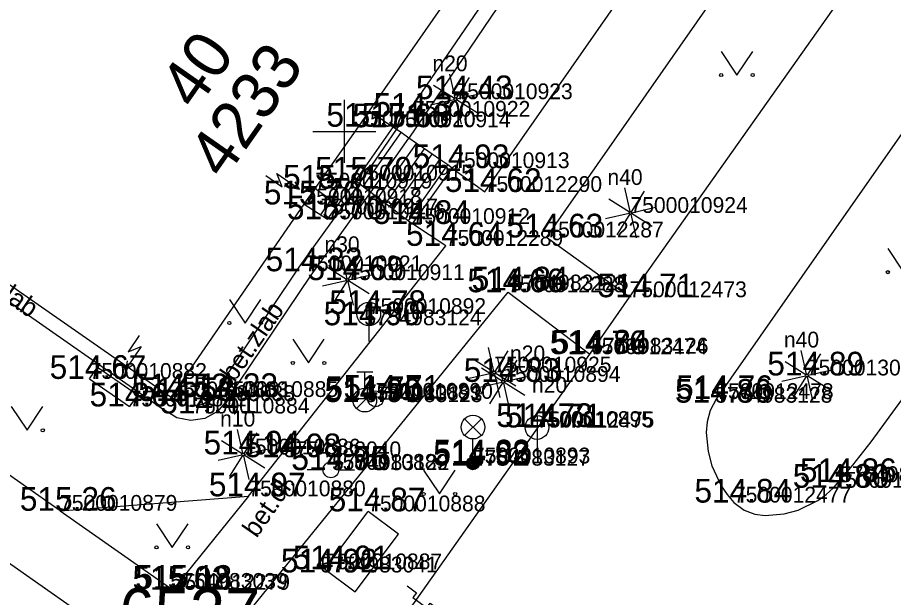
# Model space of a CAD drawing. Extents: x -669251 to -668549, y -1128351 to -1127698.
# Drawn here: x -668960.36 to -668932.59, y -1127964.76 to -1127946.39 of the extents above; entities that cross this region are included whole.
import ezdxf

# ---------------------------------------------------------------- set-up
doc = ezdxf.new("R2010")
doc.units = 0
for name, color, linetype in [('Vrstva 1', 7, 'Continuous'), ('Vrstva 10', 7, 'Continuous'), ('Vrstva 11', 7, 'Continuous'), ('Vrstva 14', 7, 'Continuous'), ('Vrstva 2', 7, 'Continuous'), ('Vrstva 22', 7, 'Continuous'), ('Vrstva 24', 7, 'Continuous'), ('Vrstva 27', 7, 'Continuous'), ('Vrstva 28', 7, 'Continuous'), ('Vrstva 3', 7, 'Continuous'), ('Vrstva 33', 7, 'Continuous'), ('Vrstva 36', 7, 'Continuous'), ('Vrstva 40', 7, 'Continuous'), ('Vrstva 43', 7, 'Continuous'), ('Vrstva 44', 7, 'Continuous'), ('Vrstva 47', 7, 'Continuous'), ('Vrstva 5', 7, 'Continuous'), ('Vrstva 6', 7, 'Continuous'), ('Vrstva 61', 7, 'Continuous'), ('Vrstva 63', 7, 'Continuous')]:
    doc.layers.add(name, color=color, linetype=linetype)

msp = doc.modelspace()

# ---------------------------------------------------------------- linework, layer by layer
at = {"layer": 'Vrstva 1'}
for p, q in [((-668946.478, -1127948.979), (-668946.478, -1127948.979)), ((-668947.823, -1127949.536), (-668947.823, -1127949.536)), ((-668949.554, -1127949.85), (-668949.554, -1127949.85)), ((-668948.449, -1127949.868), (-668948.449, -1127949.868)), ((-668946.578, -1127951.163), (-668946.578, -1127951.163)), ((-668949.639, -1127951.558), (-668949.639, -1127951.558)), ((-668950.927, -1127951.811), (-668950.927, -1127951.811)), ((-668945.547, -1127951.918), (-668945.547, -1127951.918)), ((-668951.264, -1127952.313), (-668951.264, -1127952.313)), ((-668950.752, -1127952.627), (-668950.752, -1127952.627)), ((-668940.929, -1127952.582), (-668940.929, -1127952.582)), ((-668950.533, -1127952.785), (-668950.533, -1127952.785)), ((-668947.834, -1127952.932), (-668947.834, -1127952.932)), ((-668943.593, -1127953.358), (-668943.593, -1127953.358)), ((-668946.78, -1127953.625), (-668946.78, -1127953.625)), ((-668951.243, -1127954.43), (-668951.243, -1127954.43)), ((-668949.9, -1127954.71), (-668949.9, -1127954.71)), ((-668944.811, -1127955.095), (-668944.811, -1127955.095)), ((-668944.71, -1127955.038), (-668944.71, -1127955.038)), ((-668940.958, -1127955.253), (-668940.958, -1127955.253)), ((-668949.225, -1127955.784), (-668949.225, -1127955.784)), ((-668949.367, -1127956.141), (-668949.367, -1127956.141)), ((-668942.213, -1127957.057), (-668942.213, -1127957.057)), ((-668942.174, -1127957.038), (-668942.174, -1127957.038)), ((-668945.249, -1127957.636), (-668945.249, -1127957.636)), ((-668958.076, -1127957.84), (-668958.076, -1127957.84)), ((-668944.963, -1127957.935), (-668944.963, -1127957.935)), ((-668935.335, -1127957.731), (-668935.335, -1127957.731)), ((-668955.487, -1127958.423), (-668955.487, -1127958.423)), ((-668953.915, -1127958.413), (-668953.915, -1127958.413)), ((-668949.01, -1127958.47), (-668949.01, -1127958.47)), ((-668938.208, -1127958.478), (-668938.208, -1127958.478)), ((-668956.81, -1127958.713), (-668956.81, -1127958.713)), ((-668955.283, -1127958.542), (-668955.283, -1127958.542)), ((-668949.35, -1127958.513), (-668949.35, -1127958.513)), ((-668949.34, -1127958.574), (-668949.34, -1127958.574)), ((-668938.245, -1127958.594), (-668938.245, -1127958.594)), ((-668954.822, -1127958.936), (-668954.822, -1127958.936)), ((-668943.933, -1127959.364), (-668943.933, -1127959.364)), ((-668943.891, -1127959.38), (-668943.891, -1127959.38)), ((-668953.208, -1127960.235), (-668953.208, -1127960.235)), ((-668951.916, -1127960.321), (-668951.916, -1127960.321)), ((-668950.425, -1127960.72), (-668950.425, -1127960.72)), ((-668945.932, -1127960.588), (-668945.932, -1127960.588)), ((-668945.921, -1127960.518), (-668945.921, -1127960.518)), ((-668950.391, -1127960.731), (-668950.391, -1127960.731)), ((-668934.283, -1127961.109), (-668934.283, -1127961.109)), ((-668953.041, -1127961.56), (-668953.041, -1127961.56)), ((-668934.496, -1127961.289), (-668934.496, -1127961.289)), ((-668937.649, -1127961.759), (-668937.649, -1127961.759)), ((-668959.013, -1127962.018), (-668959.013, -1127962.018)), ((-668949.244, -1127962.037), (-668949.244, -1127962.037)), ((-668950.757, -1127963.972), (-668950.757, -1127963.972)), ((-668950.618, -1127963.872), (-668950.618, -1127963.872)), ((-668955.515, -1127964.491), (-668955.515, -1127964.491)), ((-668955.442, -1127964.522), (-668955.442, -1127964.522))]:
    msp.add_line(p, q, dxfattribs=at)
at = {"layer": 'Vrstva 10'}
for p, q in [((-668939.036, -1127937.065), (-668947.956, -1127950.209)), ((-668948.347, -1127949.939), (-668940.177, -1127938.02)), ((-668945.547, -1127951.918), (-668936.445, -1127938.885)), ((-668943.593, -1127953.358), (-668934.469, -1127940.308)), ((-668940.958, -1127955.253), (-668934.167, -1127945.646)), ((-668949.52, -1127951.649), (-668948.347, -1127949.939)), ((-668946.578, -1127951.163), (-668945.547, -1127951.918)), ((-668951.43, -1127954.305), (-668949.52, -1127951.649)), ((-668951.056, -1127954.555), (-668949.161, -1127951.922)), ((-668965.097, -1127952.276), (-668955.699, -1127958.834)), ((-668946.78, -1127953.625), (-668947.834, -1127952.932)), ((-668940.958, -1127955.253), (-668943.593, -1127953.358)), ((-668953.041, -1127961.56), (-668946.78, -1127953.625)), ((-668954.108, -1127958.297), (-668951.43, -1127954.305)), ((-668953.722, -1127958.529), (-668951.056, -1127954.555)), ((-668954.992, -1127967.628), (-668944.811, -1127955.095)), ((-668944.811, -1127955.095), (-668942.213, -1127957.057)), ((-668942.213, -1127957.057), (-668940.958, -1127955.253)), ((-668953.041, -1127961.56), (-668955.442, -1127964.522)), ((-668959.013, -1127962.018), (-668955.442, -1127964.522))]:
    msp.add_line(p, q, dxfattribs=at)
for points in [[(-668930.916, -1127948.056), (-668934.562, -1127953.267), (-668938.208, -1127958.478), (-668938.4, -1127958.846), (-668938.494, -1127959.204), (-668938.524, -1127959.537), (-668938.47, -1127960.14), (-668938.349, -1127960.59), (-668938.055, -1127961.223), (-668937.864, -1127961.507), (-668937.649, -1127961.759), (-668937.322, -1127961.999), (-668936.983, -1127962.121), (-668936.658, -1127962.165), (-668936.058, -1127962.12), (-668935.608, -1127961.996), (-668934.986, -1127961.695), (-668934.72, -1127961.503), (-668934.496, -1127961.289), (-668933.884, -1127960.578), (-668933.298, -1127959.833), (-668931.64, -1127957.566)], [(-668959.013, -1127962.018), (-668967.919, -1127955.77)], [(-668969.098, -1127957.738), (-668962.045, -1127962.683), (-668954.992, -1127967.628), (-668954.609, -1127967.856), (-668954.246, -1127968.014), (-668953.566, -1127968.2), (-668953.035, -1127968.266), (-668952.24, -1127968.256), (-668951.488, -1127968.119), (-668950.77, -1127967.878), (-668950.239, -1127967.633), (-668949.859, -1127967.411), (-668949.342, -1127967.014), (-668948.918, -1127966.536), (-668945.566, -1127961.796), (-668942.213, -1127957.057)], [(-668955.487, -1127958.423), (-668955.188, -1127958.64), (-668954.826, -1127958.711), (-668954.467, -1127958.625), (-668954.178, -1127958.396), (-668954.108, -1127958.297)], [(-668953.722, -1127958.529), (-668954.02, -1127958.872), (-668954.418, -1127959.091), (-668954.867, -1127959.161), (-668955.312, -1127959.071), (-668955.699, -1127958.834)]]:
    msp.add_lwpolyline(points, dxfattribs=at)
at = {"layer": 'Vrstva 11'}
for p, q in [((-668949.201, -1127949.344), (-668948.449, -1127949.868)), ((-668949.639, -1127951.558), (-668948.449, -1127949.868)), ((-668948.347, -1127949.939), (-668948.449, -1127949.868)), ((-668949.4, -1127951.74), (-668948.202, -1127950.039)), ((-668948.202, -1127950.039), (-668948.347, -1127949.939)), ((-668947.956, -1127950.209), (-668948.202, -1127950.039)), ((-668949.161, -1127951.922), (-668947.956, -1127950.209)), ((-668948.922, -1127952.104), (-668947.709, -1127950.38)), ((-668947.709, -1127950.38), (-668947.956, -1127950.209)), ((-668947.462, -1127950.551), (-668947.709, -1127950.38)), ((-668948.684, -1127952.285), (-668947.462, -1127950.551)), ((-668948.445, -1127952.467), (-668947.216, -1127950.722)), ((-668947.216, -1127950.722), (-668947.462, -1127950.551)), ((-668946.969, -1127950.892), (-668947.216, -1127950.722)), ((-668948.206, -1127952.649), (-668946.969, -1127950.892)), ((-668946.722, -1127951.063), (-668946.969, -1127950.892)), ((-668947.967, -1127952.831), (-668946.722, -1127951.063)), ((-668947.834, -1127952.932), (-668946.578, -1127951.163)), ((-668946.578, -1127951.163), (-668946.722, -1127951.063)), ((-668950.533, -1127952.785), (-668949.639, -1127951.558)), ((-668949.639, -1127951.558), (-668949.52, -1127951.649)), ((-668949.52, -1127951.649), (-668949.4, -1127951.74)), ((-668949.4, -1127951.74), (-668949.161, -1127951.922)), ((-668949.161, -1127951.922), (-668948.922, -1127952.104)), ((-668948.922, -1127952.104), (-668948.684, -1127952.285)), ((-668951.27, -1127952.309), (-668950.533, -1127952.785)), ((-668948.684, -1127952.285), (-668948.445, -1127952.467)), ((-668948.445, -1127952.467), (-668948.206, -1127952.649)), ((-668948.206, -1127952.649), (-668947.967, -1127952.831)), ((-668947.967, -1127952.831), (-668947.834, -1127952.932))]:
    msp.add_line(p, q, dxfattribs=at)
at = {"layer": 'Vrstva 14'}
msp.add_line((-668959.013, -1127962.018), (-668953.041, -1127961.56), dxfattribs=at)
at = {"layer": 'Vrstva 22'}
for p, q in [((-668946.486, -1127948.939), (-668946.658, -1127948.185)), ((-668946.044, -1127948.289), (-668946.458, -1127948.945)), ((-668946.512, -1127948.959), (-668947.168, -1127948.545)), ((-668947.272, -1127949.159), (-668946.518, -1127948.987)), ((-668946.498, -1127949.013), (-668946.912, -1127949.669)), ((-668946.47, -1127949.019), (-668946.298, -1127949.773)), ((-668945.788, -1127949.413), (-668946.444, -1127948.999)), ((-668946.438, -1127948.971), (-668945.684, -1127948.799)), ((-668940.937, -1127952.542), (-668941.109, -1127951.788)), ((-668940.495, -1127951.892), (-668940.909, -1127952.548)), ((-668940.963, -1127952.562), (-668941.619, -1127952.148)), ((-668941.723, -1127952.762), (-668940.969, -1127952.59)), ((-668940.949, -1127952.616), (-668941.363, -1127953.272)), ((-668940.921, -1127952.622), (-668940.749, -1127953.376)), ((-668940.239, -1127953.016), (-668940.895, -1127952.602)), ((-668940.889, -1127952.574), (-668940.135, -1127952.402)), ((-668949.908, -1127954.67), (-668950.08, -1127953.916)), ((-668949.466, -1127954.02), (-668949.88, -1127954.676)), ((-668949.934, -1127954.69), (-668950.59, -1127954.276)), ((-668949.86, -1127954.702), (-668949.106, -1127954.53)), ((-668950.694, -1127954.89), (-668949.94, -1127954.718)), ((-668949.92, -1127954.744), (-668950.334, -1127955.4)), ((-668949.892, -1127954.75), (-668949.72, -1127955.504)), ((-668949.21, -1127955.144), (-668949.866, -1127954.73)), ((-668945.257, -1127957.596), (-668945.429, -1127956.842)), ((-668944.815, -1127956.946), (-668945.229, -1127957.602)), ((-668935.343, -1127957.691), (-668935.515, -1127956.937)), ((-668934.901, -1127957.041), (-668935.315, -1127957.697)), ((-668945.283, -1127957.616), (-668945.939, -1127957.202)), ((-668944.971, -1127957.895), (-668945.143, -1127957.141)), ((-668944.529, -1127957.245), (-668944.943, -1127957.901)), ((-668935.369, -1127957.711), (-668936.025, -1127957.297)), ((-668946.043, -1127957.816), (-668945.289, -1127957.644)), ((-668945.269, -1127957.67), (-668945.683, -1127958.326)), ((-668944.997, -1127957.915), (-668945.653, -1127957.501)), ((-668944.559, -1127958.07), (-668945.215, -1127957.656)), ((-668945.209, -1127957.628), (-668944.455, -1127957.456)), ((-668935.295, -1127957.723), (-668934.541, -1127957.551)), ((-668945.757, -1127958.115), (-668945.003, -1127957.943)), ((-668945.241, -1127957.676), (-668945.069, -1127958.43)), ((-668944.923, -1127957.927), (-668944.169, -1127957.755)), ((-668936.129, -1127957.911), (-668935.375, -1127957.739)), ((-668935.355, -1127957.765), (-668935.769, -1127958.421)), ((-668935.327, -1127957.771), (-668935.155, -1127958.525)), ((-668934.645, -1127958.165), (-668935.301, -1127957.751)), ((-668944.983, -1127957.969), (-668945.397, -1127958.625)), ((-668944.955, -1127957.975), (-668944.783, -1127958.729)), ((-668944.273, -1127958.369), (-668944.929, -1127957.955)), ((-668953.216, -1127960.195), (-668953.388, -1127959.441)), ((-668952.774, -1127959.545), (-668953.188, -1127960.201)), ((-668953.242, -1127960.215), (-668953.898, -1127959.801)), ((-668953.168, -1127960.227), (-668952.414, -1127960.055)), ((-668954.002, -1127960.415), (-668953.248, -1127960.243)), ((-668953.228, -1127960.269), (-668953.642, -1127960.925)), ((-668953.2, -1127960.275), (-668953.028, -1127961.029)), ((-668952.518, -1127960.669), (-668953.174, -1127960.255))]:
    msp.add_line(p, q, dxfattribs=at)
for centre in [(-668946.478, -1127948.979), (-668940.929, -1127952.582), (-668949.9, -1127954.71), (-668945.249, -1127957.636), (-668944.963, -1127957.935), (-668935.335, -1127957.731), (-668953.208, -1127960.235)]:
    msp.add_circle(centre, 0.04, dxfattribs=at)
at = {"layer": 'Vrstva 24'}
for p, q in [((-668952.486, -1127951.396), (-668951.971, -1127951.752)), ((-668951.971, -1127951.752), (-668952.137, -1127951.333)), ((-668952.137, -1127951.333), (-668951.417, -1127951.83)), ((-668951.681, -1127951.781), (-668951.417, -1127951.83)), ((-668951.417, -1127951.83), (-668951.556, -1127951.6)), ((-668950.927, -1127951.811), (-668950.428, -1127952.157)), ((-668950.427, -1127952.156), (-668950.76, -1127952.638)), ((-668956.499, -1127956.466), (-668956.854, -1127956.982)), ((-668956.436, -1127956.815), (-668956.932, -1127957.535)), ((-668956.854, -1127956.982), (-668956.436, -1127956.815)), ((-668956.884, -1127957.271), (-668956.932, -1127957.535)), ((-668956.932, -1127957.535), (-668956.703, -1127957.396)), ((-668958.076, -1127957.84), (-668957.821, -1127957.47)), ((-668957.821, -1127957.47), (-668956.555, -1127958.342)), ((-668958.076, -1127957.84), (-668956.811, -1127958.712)), ((-668956.555, -1127958.342), (-668956.811, -1127958.712)), ((-668950.618, -1127963.872), (-668949.244, -1127962.037)), ((-668948.284, -1127962.757), (-668949.245, -1127962.038)), ((-668949.657, -1127964.591), (-668948.284, -1127962.757)), ((-668950.618, -1127963.872), (-668949.657, -1127964.591))]:
    msp.add_line(p, q, dxfattribs=at)
msp.add_lwpolyline([(-668948.01, -1127964.393), (-668947.716, -1127964.615), (-668947.826, -1127964.761), (-668947.384, -1127965.092), (-668947.274, -1127964.946), (-668946.978, -1127965.166)], dxfattribs=at)
at = {"layer": 'Vrstva 27'}
for p, q in [((-668949.225, -1127955.409), (-668949.225, -1127956.659)), ((-668943.891, -1127959.005), (-668943.891, -1127960.255))]:
    msp.add_line(p, q, dxfattribs=at)
for centre in [(-668949.225, -1127955.784), (-668943.891, -1127959.38)]:
    msp.add_circle(centre, 0.375, dxfattribs=at)
at = {"layer": 'Vrstva 28'}
for p, q in [((-668949.6, -1127957.613), (-668949.1, -1127957.613)), ((-668949.35, -1127958.138), (-668949.35, -1127957.613)), ((-668949.26, -1127958.47), (-668949.76, -1127958.47)), ((-668949.615, -1127958.778), (-668949.085, -1127958.248)), ((-668948.76, -1127958.47), (-668948.26, -1127958.47)), ((-668950.675, -1127960.72), (-668951.175, -1127960.72)), ((-668950.175, -1127960.72), (-668949.675, -1127960.72))]:
    msp.add_line(p, q, dxfattribs=at)
for centre, radius in [((-668949.35, -1127958.513), 0.375), ((-668949.01, -1127958.47), 0.25), ((-668950.425, -1127960.72), 0.25)]:
    msp.add_circle(centre, radius, dxfattribs=at)
at = {"layer": 'Vrstva 33'}
for p, q in [((-668946.186, -1127959.103), (-668945.656, -1127959.633)), ((-668946.186, -1127959.633), (-668945.656, -1127959.103)), ((-668945.921, -1127960.518), (-668945.921, -1127959.743))]:
    msp.add_line(p, q, dxfattribs=at)
for centre, radius in [((-668945.921, -1127959.368), 0.375), ((-668945.921, -1127960.518), 0.2), ((-668945.921, -1127960.518), 0.18), ((-668945.921, -1127960.518), 0.16), ((-668945.921, -1127960.518), 0.14), ((-668945.921, -1127960.518), 0.12), ((-668945.921, -1127960.518), 0.1), ((-668945.921, -1127960.518), 0.08), ((-668945.921, -1127960.518), 0.06), ((-668945.921, -1127960.518), 0.04), ((-668945.921, -1127960.518), 0.02)]:
    msp.add_circle(centre, radius, dxfattribs=at)
at = {"layer": 'Vrstva 36'}
for p, q in [((-668938.054, -1127947.463), (-668937.554, -1127948.213)), ((-668937.554, -1127948.213), (-668937.054, -1127947.463)), ((-668932.771, -1127953.709), (-668932.271, -1127954.459)), ((-668953.645, -1127955.321), (-668953.145, -1127956.071)), ((-668953.145, -1127956.071), (-668952.645, -1127955.321)), ((-668951.634, -1127956.586), (-668951.134, -1127957.336)), ((-668951.134, -1127957.336), (-668950.634, -1127956.586)), ((-668960.56, -1127958.718), (-668960.06, -1127959.468)), ((-668960.06, -1127959.468), (-668959.56, -1127958.718)), ((-668947.486, -1127960.736), (-668946.986, -1127961.486)), ((-668946.986, -1127961.486), (-668946.486, -1127960.736)), ((-668955.954, -1127962.428), (-668955.454, -1127963.178)), ((-668955.454, -1127963.178), (-668954.954, -1127962.428))]:
    msp.add_line(p, q, dxfattribs=at)
for centre in [(-668938.054, -1127948.213), (-668937.054, -1127948.213), (-668932.771, -1127954.459), (-668953.645, -1127956.071), (-668952.645, -1127956.071), (-668951.634, -1127957.336), (-668950.634, -1127957.336), (-668959.56, -1127959.468), (-668947.486, -1127961.486), (-668946.486, -1127961.486), (-668955.954, -1127963.178), (-668954.954, -1127963.178)]:
    msp.add_circle(centre, 0.05, dxfattribs=at)
at = {"layer": 'Vrstva 5'}
for p, q in [((-668949.201, -1127949.344), (-668940.95, -1127937.515)), ((-668949.554, -1127949.85), (-668949.201, -1127949.344)), ((-668951.27, -1127952.309), (-668950.927, -1127951.811)), ((-668964.84, -1127951.907), (-668955.487, -1127958.423)), ((-668955.487, -1127958.423), (-668951.27, -1127952.309))]:
    msp.add_line(p, q, dxfattribs=at)
at = {"layer": 'Vrstva 6'}
msp.add_line((-668950.927, -1127951.811), (-668949.554, -1127949.85), dxfattribs=at)
at = {"layer": 'Vrstva 61'}
for p, q in [((-668950, -1127949), (-668950, -1127951)), ((-668951, -1127950), (-668949, -1127950))]:
    msp.add_line(p, q, dxfattribs=at)

# ---------------------------------------------------------------- texts
at = {"layer": 'Vrstva 2'}
for s, p in [('7500010923', (-668946.478, -1127948.979)), ('7500010922', (-668947.823, -1127949.536)), ('7500010920', (-668949.554, -1127949.85)), ('7500010914', (-668948.449, -1127949.868)), ('7500010913', (-668946.578, -1127951.163)), ('7500010915', (-668949.639, -1127951.558)), ('7500010919', (-668950.927, -1127951.811)), ('7500012290', (-668945.547, -1127951.918)), ('7500010918', (-668951.264, -1127952.313)), ('7500010917', (-668950.752, -1127952.627)), ('7500010924', (-668940.929, -1127952.582)), ('7500010916', (-668950.533, -1127952.785)), ('7500010912', (-668947.834, -1127952.932)), ('7500012287', (-668943.593, -1127953.358)), ('7500012289', (-668946.78, -1127953.625)), ('7500010921', (-668951.243, -1127954.43)), ('7500010911', (-668949.9, -1127954.71)), ('7500012288', (-668944.811, -1127955.095)), ('5754983125', (-668944.71, -1127955.038)), ('7500012473', (-668940.958, -1127955.253)), ('7500010892', (-668949.225, -1127955.784)), ('5754983124', (-668949.367, -1127956.141)), ('7500012474', (-668942.213, -1127957.057)), ('5754983126', (-668942.174, -1127957.038)), ('7500010882', (-668958.076, -1127957.84)), ('7500010925', (-668945.249, -1127957.636)), ('7500013046', (-668935.335, -1127957.731)), ('7500010894', (-668944.963, -1127957.935)), ('7500010883', (-668955.487, -1127958.423)), ('7500010885', (-668953.915, -1127958.413)), ('7500010881', (-668956.81, -1127958.713)), ('5754983038', (-668955.283, -1127958.542)), ('7500010891', (-668949.35, -1127958.513)), ('5754983123', (-668949.34, -1127958.574)), ('7500010890', (-668949.01, -1127958.47)), ('5754983128', (-668938.245, -1127958.594)), ('7500012478', (-668938.208, -1127958.478)), ('7500010884', (-668954.822, -1127958.936)), ('7500010895', (-668943.933, -1127959.364)), ('7500012475', (-668943.891, -1127959.38)), ('7500010886', (-668953.208, -1127960.235)), ('5754983040', (-668951.916, -1127960.321)), ('5754983127', (-668945.932, -1127960.588)), ('7500010893', (-668945.921, -1127960.518)), ('7500010889', (-668950.425, -1127960.72)), ('5754983122', (-668950.391, -1127960.731)), ('5754983130', (-668934.283, -1127961.109)), ('7500012476', (-668934.496, -1127961.289)), ('7500010880', (-668953.041, -1127961.56)), ('7500012477', (-668937.649, -1127961.759)), ('7500010879', (-668959.013, -1127962.018)), ('7500010888', (-668949.244, -1127962.037)), ('5754983041', (-668950.757, -1127963.972)), ('7500010887', (-668950.618, -1127963.872)), ('5754983039', (-668955.515, -1127964.491)), ('7500012279', (-668955.442, -1127964.522))]:
    msp.add_text(s, height=0.5, dxfattribs=at).set_placement(p)
at = {"layer": 'Vrstva 3'}
for s, p in [('514.43 ', (-668947.73, -1127948.979)), ('514.37 ', (-668949.075, -1127949.536)), ('515.71 ', (-668950.569, -1127949.85)), ('515.66 ', (-668949.737, -1127949.868)), ('514.93 ', (-668947.832, -1127951.163)), ('515.70 ', (-668950.927, -1127951.558)), ('515.71 ', (-668951.942, -1127951.811)), ('514.62 ', (-668946.813, -1127951.918)), ('515.70 ', (-668952.552, -1127952.313)), ('515.70 ', (-668951.821, -1127952.785)), ('514.84 ', (-668949.086, -1127952.932)), ('514.63 ', (-668944.859, -1127953.358)), ('514.64 ', (-668948.046, -1127953.625)), ('514.32 ', (-668952.495, -1127954.43)), ('514.69 ', (-668951.169, -1127954.71)), ('514.66 ', (-668946.099, -1127955.095)), ('514.84 ', (-668945.962, -1127955.038)), ('514.71 ', (-668941.973, -1127955.253)), ('514.78 ', (-668950.477, -1127955.784)), ('514.90 ', (-668950.657, -1127956.141)), ('514.84 ', (-668943.426, -1127957.038)), ('514.76 ', (-668943.487, -1127957.057)), ('514.67 ', (-668959.342, -1127957.84)), ('514.89 ', (-668936.59, -1127957.731)), ('514.83 ', (-668946.215, -1127957.935)), ('514.52 ', (-668956.739, -1127958.423)), ('514.33 ', (-668955.167, -1127958.413)), ('514.64 ', (-668958.076, -1127958.713)), ('514.58 ', (-668956.535, -1127958.542)), ('514.90 ', (-668950.63, -1127958.574)), ('514.75 ', (-668950.602, -1127958.513)), ('514.71 ', (-668950.025, -1127958.47)), ('514.86 ', (-668939.519, -1127958.594)), ('514.76 ', (-668939.482, -1127958.478)), ('514.41 ', (-668955.837, -1127958.936)), ('514.73 ', (-668945.185, -1127959.364)), ('514.71 ', (-668944.906, -1127959.38)), ('514.94 ', (-668954.462, -1127960.235)), ('514.98 ', (-668953.17, -1127960.321)), ('514.92 ', (-668947.186, -1127960.588)), ('514.83 ', (-668947.173, -1127960.518)), ('514.90 ', (-668951.681, -1127960.731)), ('514.75 ', (-668951.677, -1127960.72)), ('514.86 ', (-668935.557, -1127961.109)), ('514.80 ', (-668935.784, -1127961.289)), ('514.97 ', (-668954.295, -1127961.56)), ('514.84 ', (-668938.901, -1127961.759)), ('515.26 ', (-668960.287, -1127962.018)), ('514.87 ', (-668950.496, -1127962.037)), ('514.92 ', (-668952.011, -1127963.972)), ('514.91 ', (-668951.635, -1127963.872)), ('515.02 ', (-668956.716, -1127964.522)), ('515.18 ', (-668956.625, -1127964.491))]:
    msp.add_text(s, height=0.75, dxfattribs=at).set_placement(p)
at = {"layer": 'Vrstva 40'}
for s, rotation, p in [('bet.zlab', 325.136, (-668962.278, -1127954.321)), ('bet.zlab', 55.4077, (-668953.482, -1127957.97)), ('bet.dl.', 55.136, (-668952.781, -1127962.905))]:
    msp.add_text(s, height=0.6, rotation=rotation, dxfattribs=at).set_placement(p)
at = {"layer": 'Vrstva 43'}
msp.add_text('4233', height=1.5, rotation=55.0021, dxfattribs=at).set_placement((-668953.807, -1127951.565))
at = {"layer": 'Vrstva 44'}
msp.add_text('40', height=1.5, rotation=55.0021, dxfattribs=at).set_placement((-668954.711, -1127949.37))
at = {"layer": 'Vrstva 47'}
for s, p in [('n20', (-668947.208, -1127948.093)), ('n40', (-668941.659, -1127951.696)), ('n30', (-668950.63, -1127953.824)), ('n40', (-668936.065, -1127956.845)), ('n20', (-668944.748, -1127957.283)), ('n20', (-668944.051, -1127958.28)), ('n10', (-668953.938, -1127959.349))]:
    msp.add_text(s, height=0.5, dxfattribs=at).set_placement(p)
at = {"layer": 'Vrstva 63'}
msp.add_text('6527', height=1.5, dxfattribs=at).set_placement((-668957.128, -1127965.968))

doc.saveas('drawing.dxf')
